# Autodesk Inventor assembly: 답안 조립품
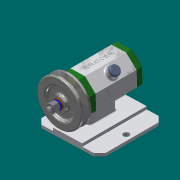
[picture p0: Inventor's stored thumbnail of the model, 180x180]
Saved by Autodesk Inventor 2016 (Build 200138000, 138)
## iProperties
Created: 2018-06
Part Number: 답안 조립품
Material: 일반
Document SubType Name: Assembly
Designer: 605-03
Author: 605-03
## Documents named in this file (16)
- C:\Users\605-03\Desktop\480608V1017\답안 조립품.iam
- C:\Users\605-03\Desktop\480608V1017\V벨트풀리.ipt
- C:\Users\605-03\Desktop\480608V1017\고무캡.ipt
- C:\Users\605-03\Desktop\480608V1017\너트 M8.ipt
- 너트 M8.ipt
- C:\Users\605-03\Desktop\480608V1017\뒤커버.ipt
- C:\Users\605-03\Desktop\480608V1017\베어링 15x32x9.ipt
- C:\Users\605-03\Desktop\480608V1017\본체.ipt
- C:\Users\605-03\Desktop\480608V1017\볼트 M4x12.ipt
- C:\Users\605-03\Desktop\480608V1017\스프링와셔 8.ipt
- C:\Users\605-03\Desktop\480608V1017\앞커버.ipt
- C:\Users\605-03\Desktop\480608V1017\오일 실 15 25 7.ipt
- C:\Users\605-03\Desktop\480608V1017\와셔 8x17.ipt
- C:\Users\605-03\Desktop\480608V1017\축.ipt
- C:\Users\605-03\Desktop\480608V1017\키 3x3x12.ipt
- 키 3x3x12.ipt
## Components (2 placed, 2 different names)
1. V벨트풀리:1
2. 고무캡:1
